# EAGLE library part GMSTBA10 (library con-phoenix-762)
PHOENIX
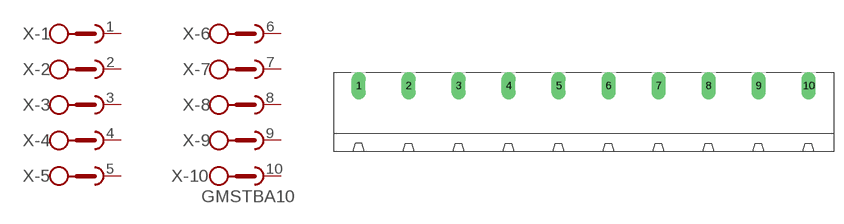
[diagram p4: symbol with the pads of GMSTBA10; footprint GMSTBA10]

Designator prefix X; gates -1=SKB -2=SKB -3=SKB -4=SKB -5=SKB -6=SKB -7=SKB -8=SKB -9=SKB -10=SKBV

## GMSTBA10 (MF: FARNELL; MPN: 1757323; OC_FARNELL: 3705249; OC_NEWARK: 71C4168)  [GMSTBA10]
1  -1:1  pas
2  -2:1  pas
3  -3:1  pas
4  -4:1  pas
5  -5:1  pas
6  -6:1  pas
7  -7:1  pas
8  -8:1  pas
9  -9:1  pas
10  -10:1  pas

## Footprint GMSTBA10 (pad centres in mm)
PHOENIX
drill 1.397 long: 1 -34.29,5.08; 2 -26.67,5.08; 3 -19.05,5.08; 4 -11.43,5.08; 5 -3.81,5.08; 6 3.81,5.08; 7 11.43,5.08; 8 19.05,5.08; 9 26.67,5.08; 10 34.29,5.08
